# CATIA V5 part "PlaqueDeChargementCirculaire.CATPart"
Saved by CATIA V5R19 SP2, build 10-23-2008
Part number: PlaqueDeChargementCirculaire
Bounding box of the stored display mesh (mm): x 0 to 10, y -35 to 35, z -34.808 to 34.808
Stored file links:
  D:\SCHOOL\FRANCE\BANC_POUTRE_EN_MOUSSE\PlaqueDeChargementCirculaire.CATPart
  C:\Program Files\Dassault Systemes\B19\intel_a\reffiles\standard\MetricThickPitch.txt
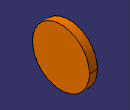
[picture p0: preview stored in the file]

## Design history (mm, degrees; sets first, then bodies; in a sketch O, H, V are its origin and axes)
AxisSystem1: origin (0, 0, 0), X (1, 0, 0), Y (0, 1, 0), Z (0, 0, 1)
Body1 (main body)
  Sketch1 on yz-plane, origin (0, 0, 0), H (0, 1, 0), V (0, 0, 1)
    circle A1 centre (0, 0) radius 35
    radius A1 = 35
  Pad1: profile Sketch1, direction (1, 0, 0), length 10
  Sketch2 on start face of Pad1, origin (0, 0, 0), H (0, 1, 0), V (0, 0, -1)
    point P1 (0, 0)
    reference projected point E1 (0, 0) from vertex [YZ plane of AxisSystem1 | ZX plane of AxisSystem1 | XY plane of AxisSystem1]
    coincidence: E1 P1
  Hole1: placed by Sketch2, at (0, 0, 0) direction (1, 0, 0), diameter 6, depth 8
  Sketch3 on start face of Pad1, origin (0, 0, 0), H (0, 1, 0), V (0, 0, -1)
    point P1 (-22, 0)
    axis line L1 (-43.2254, 0) -> (47.3252, 0)
    distance P1 O = 22
    coincidence: L1 H, P1 L1
  Hole2: placed by Sketch3, at (0, -22, 0) direction (1, 0, 0), diameter 4.917, depth 8, threaded "M6", thread diameter 6, thread depth 8, pitch 1
  RectPattern1: of Hole2, direction 1 instances 2, spacing 44, along edge [YZ plane of AxisSystem1 | XY plane of AxisSystem1]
